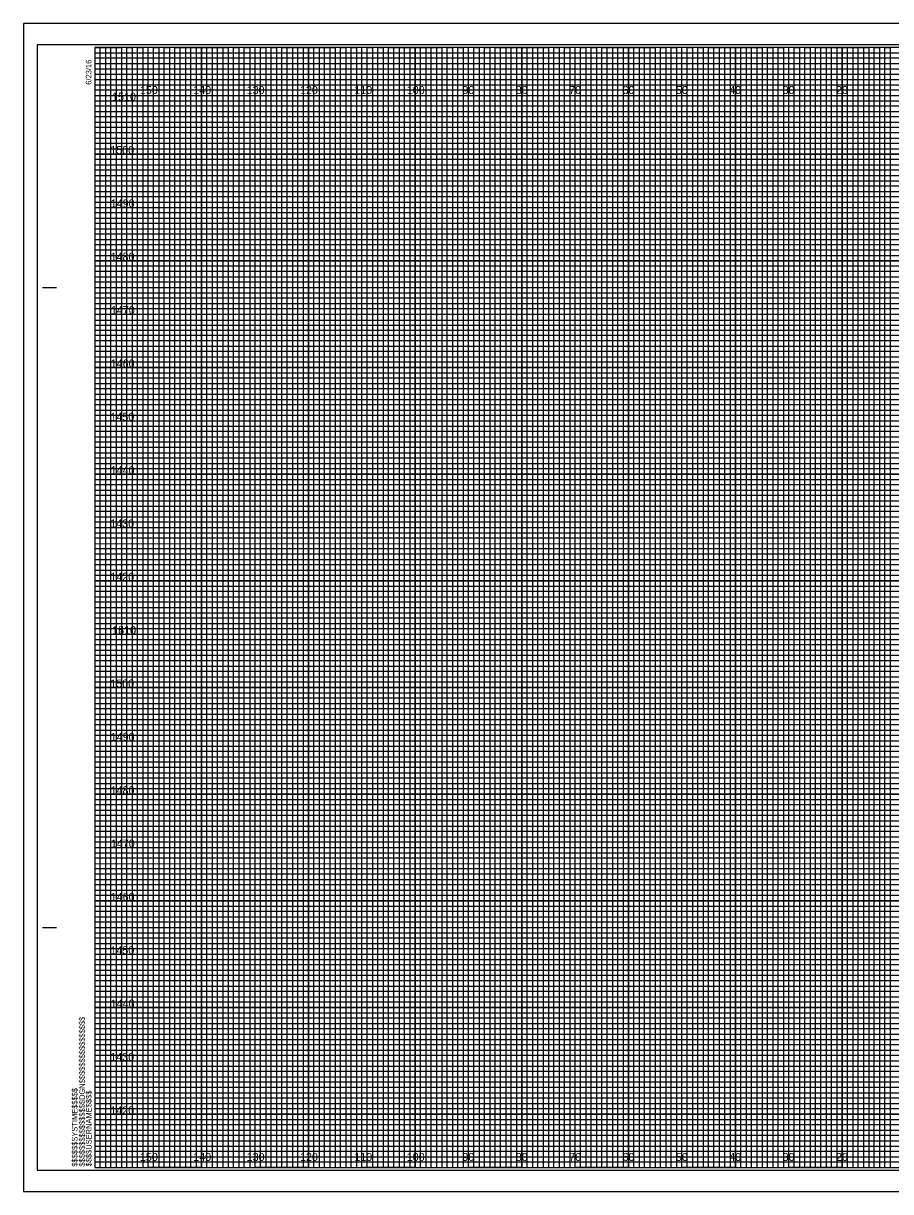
# Model space of a CAD drawing. Extents: x -13 to 323, y -5 to 215.
# Drawn here: x -13.4 to 149.1, y -4.5 to 214.5 of the extents above; entities that cross this region are included whole.
import ezdxf

# ---------------------------------------------------------------- set-up
doc = ezdxf.new("R2010")
doc.units = 0
for name, color, linetype in [('Exist Cross Section Cell', 7, 'Continuous'), ('Exist XS Center Line Elevation Label', 7, 'Continuous'), ('Exist XS Ground Line', 7, 'Continuous'), ('Prop XS EOT Tick Mark', 7, 'Continuous'), ('Prop XS Finish Grade', 7, 'Continuous'), ('Prop XS SE Text', 7, 'Continuous'), ('Prop XS Subgrade Earthwork', 7, 'Continuous'), ('Prop XSC Text', 7, 'Continuous'), ('Scratch_Level_5', 7, 'Continuous'), ('Typical Curb CELL', 7, 'Continuous'), ('Typical Guardrail CELL', 7, 'Continuous')]:
    doc.layers.add(name, color=color, linetype=linetype)

msp = doc.modelspace()

# ---------------------------------------------------------------- linework, layer by layer
at = {"layer": 'Exist Cross Section Cell'}
for points in [[(0, 210), (5, 210), (5, 0), (15, 0), (15, 210), (25, 210), (25, 0), (35, 0), (35, 210), (45, 210), (45, 0), (55, 0), (55, 210), (65, 210), (65, 0), (75, 0), (75, 210), (85, 210), (85, 0), (95, 0), (95, 210), (105, 210), (105, 0), (115, 0), (115, 210), (125, 210), (125, 0), (135, 0), (135, 210), (145, 210), (145, 0), (155, 0)], [(0, 205), (275, 205)], [(0, 185), (320, 185), (320, 195), (0, 195)], [(0, 165), (320, 165), (320, 175), (0, 175)], [(0, 145), (320, 145), (320, 155), (0, 155)], [(0, 125), (320, 125), (320, 135), (0, 135)], [(0, 105), (320, 105), (320, 115), (0, 115)], [(0, 85), (320, 85), (320, 95), (0, 95)], [(0, 65), (320, 65), (320, 75), (0, 75)], [(0, 45), (320, 45), (320, 55), (0, 55)], [(0, 25), (320, 25), (320, 35), (0, 35)], [(0, 5), (320, 5), (320, 15), (0, 15)]]:
    msp.add_lwpolyline(points, dxfattribs=at)
at = {"layer": 'Exist XS Center Line Elevation Label'}
for p, q in [((10, 210), (0, 210)), ((10, 0), (10, 210)), ((30, 210), (20, 210)), ((20, 210), (20, 0)), ((30, 0), (30, 210)), ((50, 210), (40, 210)), ((40, 210), (40, 0)), ((50, 0), (50, 210)), ((70, 210), (60, 210)), ((60, 210), (60, 0)), ((70, 0), (70, 210)), ((90, 210), (80, 210)), ((80, 210), (80, 0)), ((90, 0), (90, 210)), ((110, 210), (100, 210)), ((100, 210), (100, 0)), ((110, 0), (110, 210)), ((130, 210), (120, 210)), ((120, 210), (120, 0)), ((130, 0), (130, 210)), ((150, 210), (140, 210)), ((140, 210), (140, 0)), ((20, 0), (10, 0)), ((40, 0), (30, 0)), ((60, 0), (50, 0)), ((80, 0), (70, 0)), ((100, 0), (90, 0)), ((120, 0), (110, 0)), ((140, 0), (130, 0))]:
    msp.add_line(p, q, dxfattribs=at)
for points in [[(0, 200), (320, 200), (320, 190), (0, 190)], [(0, 180), (320, 180), (320, 170), (0, 170)], [(0, 160), (320, 160), (320, 150), (0, 150)], [(0, 140), (320, 140), (320, 130), (0, 130)], [(0, 120), (320, 120), (320, 110), (0, 110)], [(0, 100), (320, 100), (320, 90), (0, 90)], [(0, 80), (320, 80), (320, 70), (0, 70)], [(0, 60), (320, 60), (320, 50), (0, 50)], [(0, 40), (320, 40), (320, 30), (0, 30)], [(0, 20), (320, 20), (320, 10), (0, 10)]]:
    msp.add_lwpolyline(points, dxfattribs=at)
at = {"layer": 'Prop XS EOT Tick Mark'}
for p, q in [((323.3, 214.5), (-13.4, 214.5)), ((-13.4, 214.5), (-13.4, -4.5)), ((-13.4, -4.5), (323.3, -4.5))]:
    msp.add_line(p, q, dxfattribs=at)
at = {"layer": 'Prop XS Finish Grade'}
for p, q in [((10, 0), (10, 210)), ((20, 0), (20, 210)), ((30, 0), (30, 210)), ((40, 0), (40, 210)), ((50, 0), (50, 210)), ((60, 0), (60, 210)), ((70, 0), (70, 210)), ((80, 0), (80, 210)), ((90, 0), (90, 210)), ((100, 0), (100, 210)), ((110, 0), (110, 210)), ((120, 0), (120, 210)), ((130, 0), (130, 210)), ((140, 0), (140, 210)), ((0, 200), (320, 200)), ((0, 190), (320, 190)), ((0, 180), (320, 180)), ((0, 170), (320, 170)), ((0, 160), (320, 160)), ((0, 150), (320, 150)), ((0, 140), (320, 140)), ((0, 130), (320, 130)), ((0, 120), (320, 120)), ((0, 110), (320, 110)), ((0, 100), (320, 100)), ((0, 90), (320, 90)), ((0, 80), (320, 80)), ((0, 70), (320, 70)), ((0, 60), (320, 60)), ((0, 50), (320, 50)), ((0, 40), (320, 40)), ((0, 30), (320, 30)), ((0, 20), (320, 20)), ((0, 10), (320, 10))]:
    msp.add_line(p, q, dxfattribs=at)
at = {"layer": 'Prop XS SE Text'}
for points in [[(0, 0), (1, 0), (1, 210), (2, 210), (2, 0)], [(2, 0), (3, 0), (3, 210), (4, 210), (4, 0)], [(5, 0), (6, 0), (6, 210), (7, 210), (7, 0)], [(7, 0), (8, 0), (8, 210), (9, 210), (9, 0)], [(10, 0), (11, 0), (11, 210), (12, 210), (12, 0)], [(12, 0), (13, 0), (13, 210), (14, 210), (14, 0)], [(15, 0), (16, 0), (16, 210), (17, 210), (17, 0)], [(17, 0), (18, 0), (18, 210), (19, 210), (19, 0)], [(20, 0), (21, 0), (21, 210), (22, 210), (22, 0)], [(22, 0), (23, 0), (23, 210), (24, 210), (24, 0)], [(25, 0), (26, 0), (26, 210), (27, 210), (27, 0)], [(27, 0), (28, 0), (28, 210), (29, 210), (29, 0)], [(30, 0), (31, 0), (31, 210), (32, 210), (32, 0)], [(32, 0), (33, 0), (33, 210), (34, 210), (34, 0)], [(35, 0), (36, 0), (36, 210), (37, 210), (37, 0)], [(37, 0), (38, 0), (38, 210), (39, 210), (39, 0)], [(40, 0), (41, 0), (41, 210), (42, 210), (42, 0)], [(42, 0), (43, 0), (43, 210), (44, 210), (44, 0)], [(45, 0), (46, 0), (46, 210), (47, 210), (47, 0)], [(47, 0), (48, 0), (48, 210), (49, 210), (49, 0)], [(50, 0), (51, 0), (51, 210), (52, 210), (52, 0)], [(52, 0), (53, 0), (53, 210), (54, 210), (54, 0)], [(55, 0), (56, 0), (56, 210), (57, 210), (57, 0)], [(57, 0), (58, 0), (58, 210), (59, 210), (59, 0)], [(60, 0), (61, 0), (61, 210), (62, 210), (62, 0)], [(62, 0), (63, 0), (63, 210), (64, 210), (64, 0)], [(65, 0), (66, 0), (66, 210), (67, 210), (67, 0)], [(67, 0), (68, 0), (68, 210), (69, 210), (69, 0)], [(70, 0), (71, 0), (71, 210), (72, 210), (72, 0)], [(72, 0), (73, 0), (73, 210), (74, 210), (74, 0)], [(75, 0), (76, 0), (76, 210), (77, 210), (77, 0)], [(77, 0), (78, 0), (78, 210), (79, 210), (79, 0)], [(80, 0), (81, 0), (81, 210), (82, 210), (82, 0)], [(82, 0), (83, 0), (83, 210), (84, 210), (84, 0)], [(85, 0), (86, 0), (86, 210), (87, 210), (87, 0)], [(87, 0), (88, 0), (88, 210), (89, 210), (89, 0)], [(90, 0), (91, 0), (91, 210), (92, 210), (92, 0)], [(92, 0), (93, 0), (93, 210), (94, 210), (94, 0)], [(95, 0), (96, 0), (96, 210), (97, 210), (97, 0)], [(97, 0), (98, 0), (98, 210), (99, 210), (99, 0)], [(100, 0), (101, 0), (101, 210), (102, 210), (102, 0)], [(102, 0), (103, 0), (103, 210), (104, 210), (104, 0)], [(105, 0), (106, 0), (106, 210), (107, 210), (107, 0)], [(107, 0), (108, 0), (108, 210), (109, 210), (109, 0)], [(110, 0), (111, 0), (111, 210), (112, 210), (112, 0)], [(112, 0), (113, 0), (113, 210), (114, 210), (114, 0)], [(115, 0), (116, 0), (116, 210), (117, 210), (117, 0)], [(117, 0), (118, 0), (118, 210), (119, 210), (119, 0)], [(120, 0), (121, 0), (121, 210), (122, 210), (122, 0)], [(122, 0), (123, 0), (123, 210), (124, 210), (124, 0)], [(125, 0), (126, 0), (126, 210), (127, 210), (127, 0)], [(127, 0), (128, 0), (128, 210), (129, 210), (129, 0)], [(130, 0), (131, 0), (131, 210), (132, 210), (132, 0)], [(132, 0), (133, 0), (133, 210), (134, 210), (134, 0)], [(135, 0), (136, 0), (136, 210), (137, 210), (137, 0)], [(137, 0), (138, 0), (138, 210), (139, 210), (139, 0)], [(140, 0), (141, 0), (141, 210), (142, 210), (142, 0)], [(142, 0), (143, 0), (143, 210), (144, 210), (144, 0)], [(145, 0), (146, 0), (146, 210), (147, 210), (147, 0)], [(147, 0), (148, 0), (148, 210), (149, 210), (149, 0)]]:
    msp.add_lwpolyline(points, dxfattribs=at)
at = {"layer": 'Prop XS Subgrade Earthwork'}
msp.add_lwpolyline([(-13.4, -4.5), (323.3, -4.5), (323.3, 214.5), (-13.4, 214.5)], close=True, dxfattribs=at)
at = {"layer": 'Prop XSC Text'}
for p, q in [((-9.8, 165), (-7.3, 165)), ((-9.7, 165), (-7.2, 165)), ((-9.8, 45), (-7.3, 45)), ((-9.7, 45), (-7.2, 45)), ((0, 0), (0, 0)), ((0, 0), (0, 0)), ((0, 0), (0, 0)), ((0, 0), (0, 0)), ((0, 0), (0, 0)), ((0, 0), (0, 0)), ((0, 0), (0, 0))]:
    msp.add_line(p, q, dxfattribs=at)
msp.add_lwpolyline([(320, 210), (0, 210), (0, 0), (320, 0)], close=True, dxfattribs=at)
at = {"layer": 'Scratch_Level_5'}
for p, q in [((0, 209), (260, 209)), ((260, 207.98), (0, 207.98)), ((0, 207.98), (0, 207)), ((0, 207), (260, 207)), ((260, 205.89), (0, 205.89)), ((0, 205.89), (0, 204)), ((0, 204), (320, 204))]:
    msp.add_line(p, q, dxfattribs=at)
for points in [[(0, 203), (270, 203), (320, 203), (320, 202), (0, 202)], [(0, 201), (320, 201), (320, 199), (0, 199)], [(0, 198), (320, 198), (320, 197), (0, 196.98)], [(0, 196), (320, 196), (320, 194), (0, 194)], [(0, 193), (320, 193), (320, 192), (0, 192)], [(0, 191), (320, 191), (320, 189), (0, 189)], [(0, 188), (320, 188), (320, 187), (0, 187)], [(0, 186), (320, 186), (320, 184), (0, 184)], [(0, 183), (320, 183), (320, 182), (0, 182)], [(0, 181), (320, 181), (320, 179), (0, 179)], [(0, 178), (320, 178), (320, 177), (0, 177)], [(0, 176), (320, 176), (320, 173.95), (320, 173), (320, 172), (0, 172)], [(0, 174), (320, 174), (320, 173), (0, 173)], [(0, 171), (320, 171), (320, 169), (0, 169.03)], [(0, 169.03), (320, 169), (320, 168), (0, 168)], [(0, 167), (320, 167), (320, 166), (0, 166)], [(0, 164), (320, 164), (320, 163), (0, 163)], [(0, 162), (320, 162), (320, 161), (0, 161)], [(-0.07, 158.89), (320, 158.89), (320, 157.88), (-0.07, 157.88)], [(0, 157), (320, 157), (320, 156), (0, 156)], [(0, 154), (320, 154), (320, 153), (0, 153)], [(0, 152), (320, 152), (320, 151), (0, 151)], [(0, 149), (320, 149), (320, 148), (0, 148)], [(0, 147), (320, 147), (320, 146), (0, 146)], [(0, 144), (320, 144), (320, 143), (0, 143)], [(0, 142), (320, 142), (320, 141), (0, 141)], [(0, 139), (320, 139), (319.99, 137.98), (0, 138)], [(0, 137), (320, 137), (320, 136), (0, 136)], [(0, 134), (320, 134), (320, 133), (0, 133)], [(0, 132), (320, 132), (320, 131), (0, 131)], [(0, 129), (320, 129), (320, 128), (0, 128)], [(0, 127), (320, 127), (320, 126), (0, 126)], [(0, 124), (320, 124), (320, 123), (0, 123)], [(0, 122), (320, 122), (320, 121), (0, 121)], [(0, 119), (320, 119), (320, 118), (0, 118)], [(0, 116.99), (320.07, 116.91), (320, 116), (0, 116)], [(0, 114), (320, 114), (320, 113), (0, 113)], [(0, 112), (320, 112), (320, 111), (0, 111)], [(0, 109), (320, 109), (320, 108), (0, 108)], [(0, 107), (320, 107), (320, 106), (0, 106)], [(0, 104), (320, 104), (320, 103), (0, 103)], [(0, 102), (320, 102), (320, 101), (0, 101)], [(0, 99), (320, 99), (320, 98), (0, 98)], [(0, 97), (320, 97), (320, 96), (0, 96)], [(0, 94), (320, 94), (320, 93), (0, 93)], [(0, 92), (320, 92), (320, 91), (0, 91)], [(0, 89), (320, 89), (320, 88), (0, 88)], [(0, 87), (320, 87), (320, 86), (0, 86)], [(0, 84), (320, 84), (320, 83), (0, 83)], [(0, 82), (320, 82), (320, 81), (0, 81)], [(0, 79), (320, 79), (319.99, 77.98), (0, 78)], [(0, 77), (320, 77), (320, 76), (0, 76)], [(0, 74), (320, 74), (320, 73), (0, 73)], [(0, 72), (320, 72), (320, 71), (0, 71)], [(0, 69), (320, 69), (320, 68), (0, 68)], [(0, 67), (320, 67), (320, 66), (0, 66)], [(0, 64), (320, 64), (320, 63), (0, 63)], [(0, 62), (320, 62), (320, 61), (0, 61)], [(0, 59), (320, 59), (320, 58), (0, 58)], [(0, 56.99), (320.07, 56.91), (320, 56), (0, 56)], [(0, 54), (320, 54), (320, 53), (0, 53)], [(0, 52), (320, 52), (320, 51), (0, 51)], [(0, 49), (320, 49), (320, 48), (0, 48)], [(0, 47), (320, 47), (320, 46), (0, 46)], [(0, 44), (320, 44), (320, 43), (0, 43)], [(0, 42), (320, 42), (320, 41), (0, 41)], [(0, 39), (320, 39), (320, 38), (0, 38)], [(0, 37), (320, 37), (320, 36), (0, 36)], [(0, 34), (320, 34), (320, 33), (0, 33)], [(0, 32), (320, 32), (320, 31), (0, 31)], [(0, 29), (320, 29), (320, 28), (0, 28)], [(0, 27), (320, 27), (320, 26), (0, 26)], [(0, 24), (320, 24), (320, 23), (0, 23)], [(0, 22), (320, 22), (320, 21), (0, 21)], [(0, 19), (320, 19), (320, 18), (0, 18)], [(0, 17), (320, 17), (320, 16), (0, 16)], [(0, 14), (320, 14), (320, 13), (0, 13)], [(0, 12), (320, 12), (320, 11), (0, 11)], [(0, 9), (320, 9), (320, 8), (0, 8)], [(0, 7), (320, 7), (320, 6), (0, 6)], [(0, 4), (320, 4), (320, 3), (0, 3)], [(0, 2), (320, 2), (320, 1), (0, 1)]]:
    msp.add_lwpolyline(points, dxfattribs=at)
at = {"layer": 'Typical Curb CELL'}
msp.add_lwpolyline([(-10.8, -0.5), (322.4, -0.5), (322.4, 210.5), (-10.8, 210.5)], close=True, dxfattribs=at)

# ---------------------------------------------------------------- texts
at = {"layer": 'Exist XS Ground Line'}
for s, p in [('150', (8.44, 201.25)), ('140', (18.44, 201.25)), ('130', (28.44, 201.25)), ('120', (38.44, 201.25)), ('110', (48.62, 201.25)), ('100', (58.44, 201.25)), ('90', (68.86, 201.25)), ('80', (78.86, 201.25)), ('70', (88.86, 201.25)), ('60', (98.86, 201.25)), ('50', (108.86, 201.25)), ('40', (118.86, 201.25)), ('30', (128.86, 201.25)), ('20', (138.86, 201.25)), ('150', (8.44, 1.25)), ('140', (18.44, 1.25)), ('130', (28.44, 1.25)), ('120', (38.44, 1.25)), ('110', (48.62, 1.25)), ('100', (58.44, 1.25)), ('90', (68.86, 1.25)), ('80', (78.86, 1.25)), ('70', (88.86, 1.25)), ('60', (98.86, 1.25)), ('50', (108.86, 1.25)), ('40', (118.86, 1.25)), ('30', (128.86, 1.25)), ('20', (138.86, 1.25))]:
    msp.add_text(s, height=1.5, dxfattribs=at).set_placement(p)
at = {"layer": 'Prop XSC Text'}
for s, p in [('6/23/16', (-0.65, 203)), ('$$$$$$$$$$$$$$$$DGN$$$$$$$$$$$$$$$$', (-1.88, 0.18)), ('$$$$$$SYSTIME$$$$$', (-3.26, 0.18)), ('$$$$USERNAME$$$$', (-0.62, 0.23))]:
    msp.add_text(s, height=1.05, rotation=90, dxfattribs=at).set_placement(p)
at = {"layer": 'Typical Guardrail CELL'}
for s, p in [('1510', (3.23, 200)), ('1500', (2.9, 190)), ('1490', (2.97, 180)), ('1480', (2.95, 170)), ('1470', (3, 160)), ('1460', (2.97, 150)), ('1450', (2.92, 140)), ('1440', (2.97, 130)), ('1430', (2.89, 120)), ('1420', (2.9, 110)), ('1510', (3.23, 100)), ('1410', (3.28, 100)), ('1500', (2.9, 90)), ('1490', (2.97, 80)), ('1480', (2.95, 70)), ('1470', (3, 60)), ('1460', (2.97, 50)), ('1450', (2.92, 40)), ('1440', (2.97, 30)), ('1430', (2.89, 20)), ('1420', (2.9, 10))]:
    msp.add_text(s, height=1.5, dxfattribs=at).set_placement(p)

doc.saveas('drawing.dxf')
